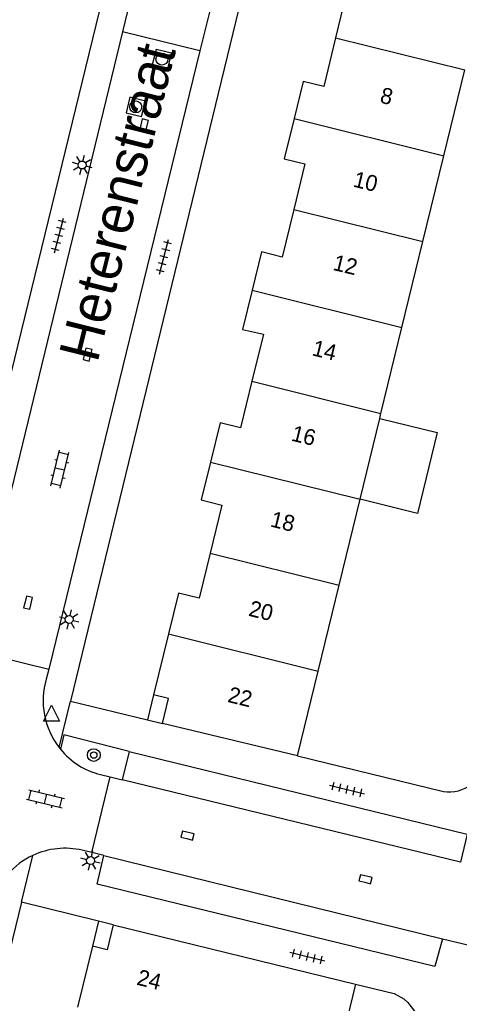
# Model space of a CAD drawing. Extents: x 128000 to 131008, y 398996 to 402500.
# Drawn here: x 128051.2 to 128078.7, y 399488 to 399549.6 of the extents above; entities that cross this region are included whole.
import ezdxf

# ---------------------------------------------------------------- set-up
doc = ezdxf.new("R2010")
doc.units = 0
for name, color, linetype in [('gg-afsc-muur', 7, 'Continuous'), ('gg-anno-huisnummerreeks BGT', 7, 'Continuous'), ('gg-anno-openbare ruimte label', 7, 'Continuous'), ('gg-bbg-gedigitaliseerde bebouwing', 7, 'Continuous'), ('gg-bbg-hoofdgebouw', 7, 'Continuous'), ('gg-bbg-luifel en loopbrug', 7, 'Continuous'), ('gg-bbg-onder overbouw', 7, 'Continuous'), ('gg-bbg-pand overbouw', 7, 'Continuous'), ('gg-bbg-tussenscheiding', 7, 'Continuous'), ('gg-knt-verharding', 7, 'Continuous'), ('gg-knt-verharding nz', 7, 'Continuous'), ('gt-grn-weggrens', 7, 'Continuous'), ('gt-symb-boom', 7, 'Continuous'), ('gt-symb-klinker verharding', 7, 'Continuous'), ('gt-symb-kolk', 7, 'Continuous'), ('gt-symb-lichtmast', 7, 'Continuous'), ('gt-symb-rioolschacht', 7, 'Continuous'), ('gt-symb-tegel verharding', 7, 'Continuous'), ('gt-symb-waterafsluiter', 7, 'Continuous')]:
    doc.layers.add(name, color=color, linetype=linetype)

# ---------------------------------------------------------------- blocks, each defined once
blk = doc.blocks.new('gt0-TEG1')
at = {"layer": 'gt-symb-tegel verharding'}
for p, q in [((-1.125, 0), (1.125, 0)), ((-0.9, -0.25), (-0.9, 0.25)), ((-0.45, -0.25), (-0.45, 0.25)), ((0, -0.25), (0, 0.25)), ((0.45, -0.25), (0.45, 0.25)), ((0.9, -0.25), (0.9, 0.25))]:
    blk.add_line(p, q, dxfattribs=at)
blk = doc.blocks.new('gt0-LMAST')
at = {"layer": 'gt-symb-lichtmast'}
for p, q in [((-0.005, 0.246), (-0.005, 0.621)), ((-0.182, 0.173), (-0.447, 0.438)), ((0.172, 0.173), (0.437, 0.438)), ((-0.255, -0.004), (-0.63, -0.004)), ((-0.182, -0.181), (-0.447, -0.446)), ((-0.005, -0.254), (-0.005, -0.629)), ((0.437, -0.446), (0.172, -0.181)), ((0.245, -0.004), (0.62, -0.004))]:
    blk.add_line(p, q, dxfattribs=at)
blk.add_circle((-0.005, -0.004), 0.25, dxfattribs=at)
blk = doc.blocks.new('gt0-KL1')
at = {"layer": 'gt-symb-klinker verharding'}
for p, q in [((-1.15, 0.3), (1.15, 0.3)), ((-1, -0.3), (-1, 0.3)), ((-0.5, 0.3), (-0.5, 0.45)), ((0, -0.3), (0, 0.3)), ((0.5, 0.3), (0.5, 0.45)), ((1, -0.3), (1, 0.3)), ((-1.15, -0.3), (1.15, -0.3)), ((-0.5, -0.45), (-0.5, -0.3)), ((0.5, -0.45), (0.5, -0.3))]:
    blk.add_line(p, q, dxfattribs=at)
blk = doc.blocks.new('gt0-KOLK')
at = {"layer": 'gt-symb-kolk'}
blk.add_lwpolyline([(0, 0), (0.375, 0), (0.375, 0.4), (-0.375, 0.4), (-0.375, 0), (0, 0)], dxfattribs=at)
blk = doc.blocks.new('gt0-RS')
at = {"layer": 'gt-symb-rioolschacht'}
blk.add_lwpolyline([(-0.5, -0.5), (0.5, -0.5), (0.5, 0.5), (-0.5, 0.5)], close=True, dxfattribs=at)
blk.add_circle((0, 0), 0.375, dxfattribs=at)
blk = doc.blocks.new('gt0-WAFSL')
at = {"layer": 'gt-symb-waterafsluiter'}
for p, q in [((-0.5, -0.333), (0, 0.667)), ((0, 0.667), (0.5, -0.333)), ((0.5, -0.333), (-0.5, -0.333))]:
    blk.add_line(p, q, dxfattribs=at)
blk = doc.blocks.new('gt0-BOOM')
at = {"layer": 'gt-symb-boom'}
for radius in [0.4, 0.2]:
    blk.add_circle((0, 0), radius, dxfattribs=at)

msp = doc.modelspace()

# ---------------------------------------------------------------- linework, layer by layer
at = {"layer": 'gg-afsc-muur'}
msp.add_line((128068.56, 399503.51), (128077.713, 399501.272), dxfattribs=at)
msp.add_lwpolyline([(128072.212, 399489.204), (128074.629, 399488.621), (128075.231, 399488.281), (128075.492, 399488.054), (128075.902, 399487.514), (128076.16, 399486.88), (128076.237, 399486.276), (128076.168, 399485.657)], dxfattribs=at)
msp.add_arc((128078.026, 399503.808), 2.555, 262.96462, 346.74429, dxfattribs=at)
at = {"layer": 'gg-bbg-gedigitaliseerde bebouwing'}
msp.add_lwpolyline([(128072.212, 399489.204), (128071.304, 399485.502), (128064.48, 399487.175), (128064.084, 399485.56)], dxfattribs=at)
at = {"layer": 'gg-bbg-hoofdgebouw'}
for p, q in [((128077.747, 399541.118), (128079.062, 399546.499)), ((128076.433, 399535.737), (128077.747, 399541.118)), ((128075.118, 399530.356), (128076.433, 399535.737)), ((128073.804, 399524.975), (128075.118, 399530.356)), ((128072.489, 399519.593), (128073.727, 399524.659)), ((128073.727, 399524.659), (128073.804, 399524.975)), ((128071.174, 399514.212), (128072.489, 399519.593)), ((128069.86, 399508.831), (128071.174, 399514.212)), ((128060.483, 399511.166), (128059.55, 399507.33)), ((128068.56, 399503.51), (128069.86, 399508.831)), ((128068.56, 399503.51), (128060.11, 399505.54)), ((128057.02, 399492.93), (128072.212, 399489.204)), ((128055.71, 399491.59), (128054.769, 399487.766))]:
    msp.add_line(p, q, dxfattribs=at)
for points in [[(128070.982, 399554.22), (128070.35, 399551.6), (128071.63, 399551.29), (128070.955, 399548.518)], [(128070.955, 399548.518), (128070.21, 399545.46), (128068.93, 399545.77), (128068.362, 399543.455)], [(128068.362, 399543.455), (128067.74, 399540.92), (128069.031, 399540.61), (128068.336, 399537.753)], [(128068.336, 399537.753), (128067.61, 399534.77), (128066.32, 399535.09), (128065.732, 399532.693)], [(128065.732, 399532.693), (128065.13, 399530.24), (128066.43, 399529.93), (128065.712, 399526.99)], [(128065.712, 399526.99), (128065.001, 399524.08), (128063.72, 399524.39), (128063.115, 399521.928)], [(128063.115, 399521.928), (128062.53, 399519.55), (128063.82, 399519.23), (128063.088, 399516.226)], [(128063.088, 399516.226), (128062.4, 399513.4), (128061.1, 399513.7), (128060.483, 399511.166)]]:
    msp.add_lwpolyline(points, dxfattribs=at)
at = {"layer": 'gg-bbg-luifel en loopbrug'}
msp.add_lwpolyline([(128073.727, 399524.659), (128077.333, 399523.776), (128076.093, 399518.711), (128072.489, 399519.593)], dxfattribs=at)
at = {"layer": 'gg-bbg-onder overbouw'}
for points in [[(128060.11, 399505.54), (128060.48, 399507.1), (128059.55, 399507.33)], [(128057.02, 399492.93), (128056.63, 399491.36), (128055.71, 399491.59)]]:
    msp.add_lwpolyline(points, dxfattribs=at)
at = {"layer": 'gg-bbg-pand overbouw'}
for p, q in [((128059.55, 399507.33), (128059.17, 399505.77)), ((128059.17, 399505.77), (128060.11, 399505.54)), ((128056.1, 399493.16), (128055.71, 399491.59)), ((128057.02, 399492.93), (128056.1, 399493.16))]:
    msp.add_line(p, q, dxfattribs=at)
at = {"layer": 'gg-bbg-tussenscheiding'}
for p, q in [((128070.955, 399548.518), (128079.062, 399546.499)), ((128068.362, 399543.455), (128077.747, 399541.118)), ((128068.336, 399537.753), (128076.433, 399535.737)), ((128065.732, 399532.693), (128075.118, 399530.356)), ((128065.712, 399526.99), (128073.804, 399524.975)), ((128063.115, 399521.928), (128072.489, 399519.593)), ((128063.088, 399516.226), (128071.174, 399514.212)), ((128060.483, 399511.166), (128069.86, 399508.831))]:
    msp.add_line(p, q, dxfattribs=at)
at = {"layer": 'gg-knt-verharding'}
for p, q in [((128068.697, 399566.024), (128054.33, 399506.95)), ((128057.051, 399553.915), (128046.06, 399508.95)), ((128058.605, 399553.01), (128057.599, 399548.879)), ((128063.461, 399551.816), (128062.454, 399547.704)), ((128057.599, 399548.879), (128048.173, 399510.139)), ((128062.454, 399547.704), (128057.599, 399548.879)), ((128062.454, 399547.704), (128052.973, 399508.957)), ((128048.173, 399510.139), (128052.973, 399508.957)), ((128052.973, 399508.957), (128052.82, 399508.33)), ((128054.33, 399506.95), (128059.17, 399505.77)), ((128053.622, 399504.036), (128053.705, 399503.933)), ((128058.017, 399503.789), (128057.581, 399502.009)), ((128055.669, 399497.453), (128056.814, 399502.196)), ((128056.219, 399502.341), (128056.814, 399502.196)), ((128056.814, 399502.196), (128057.581, 399502.009)), ((128055.669, 399497.453), (128055.069, 399497.6)), ((128056.424, 399497.268), (128055.669, 399497.453)), ((128051.27, 399494.35), (128040.705, 399451.381)), ((128056.1, 399493.16), (128051.27, 399494.35)), ((128077.667, 399492.058), (128085.234, 399490.202))]:
    msp.add_line(p, q, dxfattribs=at)
for points in [[(128058.017, 399503.789), (128053.925, 399504.84), (128053.705, 399503.933)], [(128058.017, 399503.789), (128079.213, 399498.615), (128078.797, 399496.844)], [(128077.667, 399492.058), (128077.172, 399490.318), (128056.016, 399495.479), (128056.424, 399497.268)]]:
    msp.add_lwpolyline(points, dxfattribs=at)
for centre, radius, start, end in [((128057.385, 399506.961), 4.766, 163.30222, 217.85652), ((128057.383, 399506.96), 4.764, 219.45715, 255.85447), ((128053.991, 399492.947), 4.775, 114.87375, 163.16004), ((128053.993, 399492.947), 4.775, 76.97354, 114.89953)]:
    msp.add_arc(centre, radius, start, end, dxfattribs=at)
at = {"layer": 'gg-knt-verharding nz'}
for p, q in [((128078.797, 399496.844), (128057.581, 399502.009)), ((128056.424, 399497.268), (128077.667, 399492.058))]:
    msp.add_line(p, q, dxfattribs=at)
at = {"layer": 'gt-grn-weggrens'}
for p, q in [((128053.622, 399504.036), (128054.33, 399506.95)), ((128051.27, 399494.35), (128051.982, 399497.279))]:
    msp.add_line(p, q, dxfattribs=at)

# ---------------------------------------------------------------- block references
at = {"layer": 'gt-symb-boom'}
msp.add_blockref('gt0-BOOM', (128055.798, 399503.565), dxfattribs=at)
at = {"layer": 'gt-symb-klinker verharding'}
for p, rotation in [((128053.676, 399521.48), 76.29711003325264), ((128052.776, 399500.824), -13.883418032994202)]:
    msp.add_blockref('gt0-KL1', p, dxfattribs=dict(at, rotation=rotation))
at = {"layer": 'gt-symb-kolk'}
for p, rotation in [((128058.745, 399543.061), -103.77214543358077), ((128055.218, 399528.708), -103.77214543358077), ((128051.487, 399513.159), -103.77214543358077), ((128061.621, 399498.327), -13.772145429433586), ((128072.786, 399495.592), -13.772145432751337)]:
    msp.add_blockref('gt0-KOLK', p, dxfattribs=dict(at, rotation=rotation))
at = {"layer": 'gt-symb-lichtmast'}
for p, rotation in [((128055.057, 399540.546), 76.28353067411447), ((128054.25, 399512.066), 76.28353067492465), ((128055.604, 399496.953), -13.772145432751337)]:
    msp.add_blockref('gt0-LMAST', p, dxfattribs=dict(at, rotation=rotation))
at = {"layer": 'gt-symb-rioolschacht'}
for p, rotation in [((128060.069, 399547.174), -13.772145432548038), ((128058.431, 399544.179), -13.772145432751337)]:
    msp.add_blockref('gt0-RS', p, dxfattribs=dict(at, rotation=rotation))
at = {"layer": 'gt-symb-tegel verharding'}
for p, rotation in [((128053.609, 399536.124), 75.5744682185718), ((128060.201, 399534.79), 75.5744682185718), ((128071.674, 399501.408), -13.647238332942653), ((128069.191, 399490.94), -13.702889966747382)]:
    msp.add_blockref('gt0-TEG1', p, dxfattribs=dict(at, rotation=rotation))
at = {"layer": 'gt-symb-waterafsluiter'}
msp.add_blockref('gt0-WAFSL', (128053.15, 399506.028), dxfattribs=at)

# ---------------------------------------------------------------- texts
at = {"layer": 'gg-anno-huisnummerreeks BGT'}
for s, rotation, p in [('8', 346.3, (128073.685, 399544.464)), ('10', 346.3, (128072.004, 399539.197)), ('12', 346.4, (128070.734, 399533.975)), ('14', 346.3, (128069.428, 399528.624)), ('16', 346.3, (128068.123, 399523.279)), ('18', 346.3, (128066.813, 399517.898)), ('20', 346.3, (128065.45, 399512.303)), ('22', 346.3, (128064.135, 399506.901)), ('24', 346.2, (128058.437, 399489.185))]:
    msp.add_text(s, height=1, rotation=rotation, dxfattribs=at).set_placement(p)
at = {"layer": 'gg-anno-openbare ruimte label'}
msp.add_text('Heterenstraat', height=2.5, rotation=75.9, dxfattribs=at).set_placement((128056.021, 399528.097))

doc.saveas('drawing.dxf')
